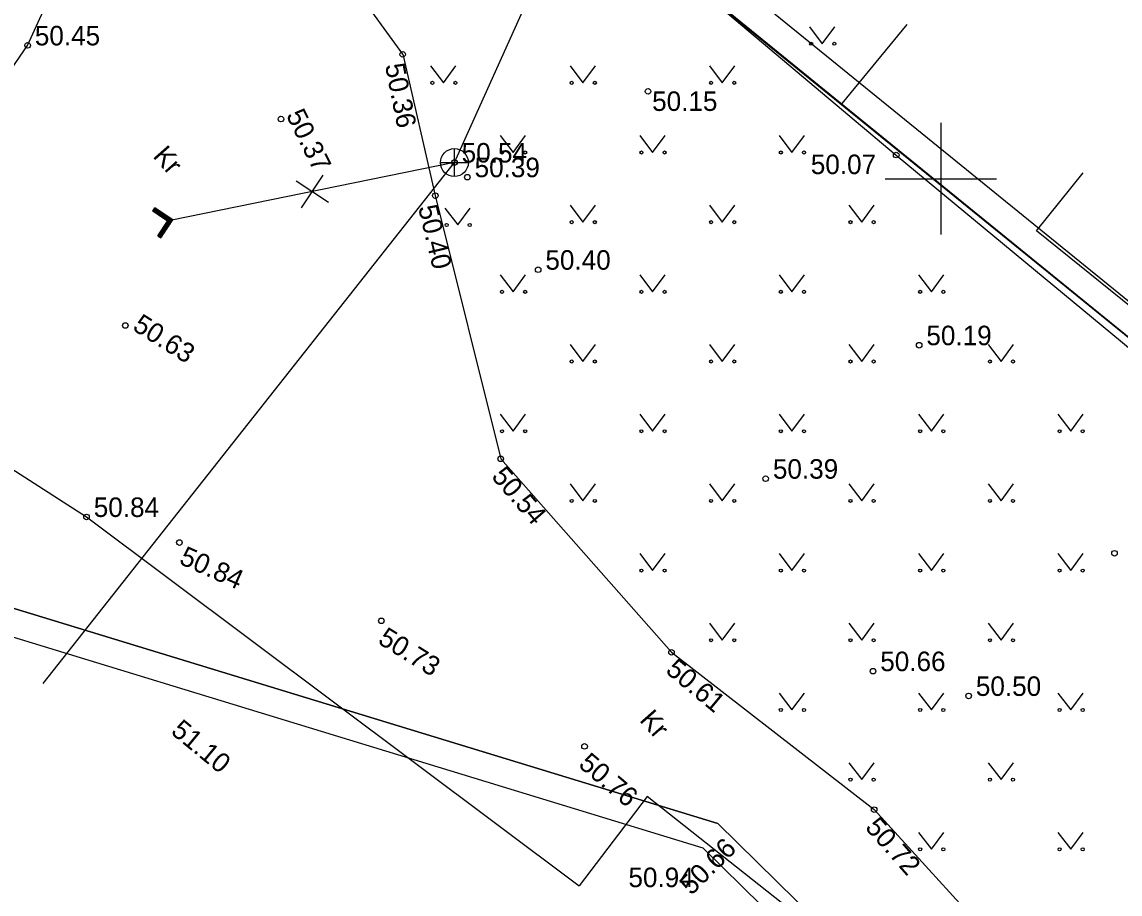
# Model space of a CAD drawing. Extents: x 640876 to 641418, y 6455595 to 6456085.
# Drawn here: x 641167.04 to 641206.43, y 6455774.33 to 6455805.62 of the extents above; entities that cross this region are included whole.
import ezdxf

# ---------------------------------------------------------------- set-up
doc = ezdxf.new("R2010")
doc.units = 0
for name, color, linetype in [('AED', 7, 'Continuous'), ('HALJASTUS', 7, 'Continuous'), ('HOONE', 7, 'Continuous'), ('KKAEV', 7, 'Continuous'), ('KORGUS', 7, 'Continuous'), ('KTRASS', 7, 'Continuous'), ('MOOTKORG', 7, 'Continuous'), ('MOOTMPUNKT', 7, 'Continuous'), ('MOOTPIIR', 7, 'Continuous'), ('PIIR', 7, 'Continuous'), ('SKTRASS', 7, 'Continuous'), ('TEE', 7, 'Continuous'), ('VORK', 7, 'Continuous')]:
    doc.layers.add(name, color=color, linetype=linetype)

msp = doc.modelspace()

# ---------------------------------------------------------------- linework, layer by layer
at = {"layer": 'AED'}
msp.add_lwpolyline([(641190.92, 6455807.146), (641198.401, 6455800.847), (641210.748, 6455790.622), (641234.804, 6455771.169), (641236.98, 6455773.379)], dxfattribs=at)
at = {"layer": 'HALJASTUS'}
for p, q in [((641195.287, 6455805.447), (641195.75, 6455804.84)), ((641195.75, 6455804.84), (641196.196, 6455805.447)), ((641181.699, 6455804.047), (641182.162, 6455803.44)), ((641182.162, 6455803.44), (641182.608, 6455804.047)), ((641186.699, 6455804.047), (641187.162, 6455803.44)), ((641187.162, 6455803.44), (641187.608, 6455804.047)), ((641191.699, 6455804.047), (641192.162, 6455803.44)), ((641192.162, 6455803.44), (641192.608, 6455804.047)), ((641184.199, 6455801.547), (641184.662, 6455800.94)), ((641184.662, 6455800.94), (641185.108, 6455801.547)), ((641189.199, 6455801.547), (641189.662, 6455800.94)), ((641189.662, 6455800.94), (641190.108, 6455801.547)), ((641194.199, 6455801.547), (641194.662, 6455800.94)), ((641194.662, 6455800.94), (641195.108, 6455801.547)), ((641182.21, 6455798.947), (641182.673, 6455798.34)), ((641182.673, 6455798.34), (641183.119, 6455798.947)), ((641186.699, 6455799.047), (641187.162, 6455798.44)), ((641187.162, 6455798.44), (641187.608, 6455799.047)), ((641191.699, 6455799.047), (641192.162, 6455798.44)), ((641192.162, 6455798.44), (641192.608, 6455799.047)), ((641196.699, 6455799.047), (641197.162, 6455798.44)), ((641197.162, 6455798.44), (641197.608, 6455799.047)), ((641184.199, 6455796.547), (641184.662, 6455795.94)), ((641184.662, 6455795.94), (641185.108, 6455796.547)), ((641189.199, 6455796.547), (641189.662, 6455795.94)), ((641189.662, 6455795.94), (641190.108, 6455796.547)), ((641194.199, 6455796.547), (641194.662, 6455795.94)), ((641194.662, 6455795.94), (641195.108, 6455796.547)), ((641199.199, 6455796.547), (641199.662, 6455795.94)), ((641199.662, 6455795.94), (641200.108, 6455796.547)), ((641186.699, 6455794.047), (641187.162, 6455793.44)), ((641187.162, 6455793.44), (641187.608, 6455794.047)), ((641191.699, 6455794.047), (641192.162, 6455793.44)), ((641192.162, 6455793.44), (641192.608, 6455794.047)), ((641196.699, 6455794.047), (641197.162, 6455793.44)), ((641197.162, 6455793.44), (641197.608, 6455794.047)), ((641201.699, 6455794.047), (641202.162, 6455793.44)), ((641202.162, 6455793.44), (641202.608, 6455794.047)), ((641184.199, 6455791.547), (641184.662, 6455790.94)), ((641184.662, 6455790.94), (641185.108, 6455791.547)), ((641189.199, 6455791.547), (641189.662, 6455790.94)), ((641189.662, 6455790.94), (641190.108, 6455791.547)), ((641194.199, 6455791.547), (641194.662, 6455790.94)), ((641194.662, 6455790.94), (641195.108, 6455791.547)), ((641199.199, 6455791.547), (641199.662, 6455790.94)), ((641199.662, 6455790.94), (641200.108, 6455791.547)), ((641204.199, 6455791.547), (641204.662, 6455790.94)), ((641204.662, 6455790.94), (641205.108, 6455791.547)), ((641186.699, 6455789.047), (641187.162, 6455788.44)), ((641187.162, 6455788.44), (641187.608, 6455789.047)), ((641191.699, 6455789.047), (641192.162, 6455788.44)), ((641192.162, 6455788.44), (641192.608, 6455789.047)), ((641196.699, 6455789.047), (641197.162, 6455788.44)), ((641197.162, 6455788.44), (641197.608, 6455789.047)), ((641201.699, 6455789.047), (641202.162, 6455788.44)), ((641202.162, 6455788.44), (641202.608, 6455789.047)), ((641189.199, 6455786.547), (641189.662, 6455785.94)), ((641189.662, 6455785.94), (641190.108, 6455786.547)), ((641194.199, 6455786.547), (641194.662, 6455785.94)), ((641194.662, 6455785.94), (641195.108, 6455786.547)), ((641199.199, 6455786.547), (641199.662, 6455785.94)), ((641199.662, 6455785.94), (641200.108, 6455786.547)), ((641204.199, 6455786.547), (641204.662, 6455785.94)), ((641204.662, 6455785.94), (641205.108, 6455786.547)), ((641191.699, 6455784.047), (641192.162, 6455783.44)), ((641192.162, 6455783.44), (641192.608, 6455784.047)), ((641196.699, 6455784.047), (641197.162, 6455783.44)), ((641197.162, 6455783.44), (641197.608, 6455784.047)), ((641201.699, 6455784.047), (641202.162, 6455783.44)), ((641202.162, 6455783.44), (641202.608, 6455784.047)), ((641194.199, 6455781.547), (641194.662, 6455780.94)), ((641194.662, 6455780.94), (641195.108, 6455781.547)), ((641199.199, 6455781.547), (641199.662, 6455780.94)), ((641199.662, 6455780.94), (641200.108, 6455781.547)), ((641204.199, 6455781.547), (641204.662, 6455780.94)), ((641204.662, 6455780.94), (641205.108, 6455781.547)), ((641196.699, 6455779.047), (641197.162, 6455778.44)), ((641197.162, 6455778.44), (641197.608, 6455779.047)), ((641201.699, 6455779.047), (641202.162, 6455778.44)), ((641202.162, 6455778.44), (641202.608, 6455779.047)), ((641199.199, 6455776.547), (641199.662, 6455775.94)), ((641199.662, 6455775.94), (641200.108, 6455776.547)), ((641204.199, 6455776.547), (641204.662, 6455775.94)), ((641204.662, 6455775.94), (641205.108, 6455776.547))]:
    msp.add_line(p, q, dxfattribs=at)
msp.add_lwpolyline([(641196.46, 6455802.7), (641198.791, 6455805.527)], dxfattribs=at)
for centre in [(641195.349, 6455804.84), (641196.178, 6455804.84), (641181.761, 6455803.44), (641182.59, 6455803.44), (641186.761, 6455803.44), (641187.59, 6455803.44), (641191.761, 6455803.44), (641192.59, 6455803.44), (641184.261, 6455800.94), (641185.09, 6455800.94), (641189.261, 6455800.94), (641190.09, 6455800.94), (641194.261, 6455800.94), (641195.09, 6455800.94), (641182.272, 6455798.34), (641183.101, 6455798.34), (641186.761, 6455798.44), (641187.59, 6455798.44), (641191.761, 6455798.44), (641192.59, 6455798.44), (641196.761, 6455798.44), (641197.59, 6455798.44), (641184.261, 6455795.94), (641185.09, 6455795.94), (641189.261, 6455795.94), (641190.09, 6455795.94), (641194.261, 6455795.94), (641195.09, 6455795.94), (641199.261, 6455795.94), (641200.09, 6455795.94), (641186.761, 6455793.44), (641187.59, 6455793.44), (641191.761, 6455793.44), (641192.59, 6455793.44), (641196.761, 6455793.44), (641197.59, 6455793.44), (641201.761, 6455793.44), (641202.59, 6455793.44), (641184.261, 6455790.94), (641185.09, 6455790.94), (641189.261, 6455790.94), (641190.09, 6455790.94), (641194.261, 6455790.94), (641195.09, 6455790.94), (641199.261, 6455790.94), (641200.09, 6455790.94), (641204.261, 6455790.94), (641205.09, 6455790.94), (641186.761, 6455788.44), (641187.59, 6455788.44), (641191.761, 6455788.44), (641192.59, 6455788.44), (641196.761, 6455788.44), (641197.59, 6455788.44), (641201.761, 6455788.44), (641202.59, 6455788.44), (641189.261, 6455785.94), (641190.09, 6455785.94), (641194.261, 6455785.94), (641195.09, 6455785.94), (641199.261, 6455785.94), (641200.09, 6455785.94), (641204.261, 6455785.94), (641205.09, 6455785.94), (641191.761, 6455783.44), (641192.59, 6455783.44), (641196.761, 6455783.44), (641197.59, 6455783.44), (641201.761, 6455783.44), (641202.59, 6455783.44), (641194.261, 6455780.94), (641195.09, 6455780.94), (641199.261, 6455780.94), (641200.09, 6455780.94), (641204.261, 6455780.94), (641205.09, 6455780.94), (641196.761, 6455778.44), (641197.59, 6455778.44), (641201.761, 6455778.44), (641202.59, 6455778.44), (641199.261, 6455775.94), (641200.09, 6455775.94), (641204.261, 6455775.94), (641205.09, 6455775.94)]:
    msp.add_circle(centre, 0.055, dxfattribs=at)
at = {"layer": 'HOONE'}
msp.add_lwpolyline([(641211.46, 6455791.66), (641203.43, 6455798.13), (641205.106, 6455800.211)], dxfattribs=at)
at = {"layer": 'KKAEV'}
for p, q in [((641182.553, 6455800.079), (641182.553, 6455801.079)), ((641182.053, 6455800.579), (641183.053, 6455800.579))]:
    msp.add_line(p, q, dxfattribs=at)
msp.add_circle((641182.553, 6455800.579), 0.5, dxfattribs=at)
at = {"layer": 'KORGUS'}
for centre in [(641180.696, 6455804.462), (641189.499, 6455803.133), (641176.329, 6455802.139), (641198.401, 6455800.847), (641183.016, 6455800.053), (641181.867, 6455799.392), (641185.556, 6455796.734), (641170.748, 6455794.733), (641199.223, 6455794.025), (641184.213, 6455789.95), (641193.717, 6455789.236), (641172.688, 6455786.945), (641206.231, 6455786.56), (641179.931, 6455784.135), (641190.34, 6455783.007), (641197.568, 6455782.332), (641200.998, 6455781.443), (641187.221, 6455779.631), (641197.609, 6455777.363)]:
    msp.add_circle(centre, 0.1, dxfattribs=at)
at = {"layer": 'KTRASS'}
for p, q in [((641182.553, 6455800.579), (641188.359, 6455813.48)), ((641167.805, 6455781.893), (641182.553, 6455800.579))]:
    msp.add_line(p, q, dxfattribs=at)
at = {"layer": 'MOOTMPUNKT'}
for centre in [(641167.241, 6455804.782), (641182.553, 6455800.579), (641169.355, 6455787.863)]:
    msp.add_circle(centre, 0.1, dxfattribs=at)
at = {"layer": 'MOOTPIIR'}
msp.add_lwpolyline([(641060.916, 6455895.936), (641100.061, 6455950.482), (641099.586, 6455952.159), (641069.132, 6455984.035), (641066.132, 6455988.623), (641076.463, 6456005.049), (641230.642, 6456010.048), (641237.36, 6455995.24), (641237.24, 6455992.81), (641236.258, 6455990.888), (641229.041, 6455971.315), (641203.026, 6455909.57), (641225.257, 6455906.847), (641239.512, 6455898.491), (641200.195, 6455851.697), (641192.016, 6455859.099), (641169.785, 6455829.138), (641192.025, 6455807.568), (641252.96, 6455758.075), (641231.388, 6455736.74), (641191.474, 6455775.975), (641152.419, 6455787.914), (641136.351, 6455788.307), (641049.066, 6455856.043)], dxfattribs=at)
at = {"layer": 'PIIR'}
for points in [[(641216.67, 6455752.61), (641192, 6455776.86), (641152.58, 6455788.91), (641136.9, 6455789.33), (641119.28, 6455802.72), (641101.72, 6455816.27), (641098.61, 6455818.83), (641124.03, 6455849.78), (641139.51, 6455868.99), (641157, 6455885.69), (641191.84, 6455860.59), (641168.46, 6455829.03), (641191.37, 6455806.79), (641234.69, 6455771.62)], [(641234.68, 6455771.59), (641191.36, 6455806.82), (641199.12, 6455815.36), (641207.91, 6455825.07), (641250.06, 6455787.79)], [(641216.67, 6455752.61), (641182.28, 6455716.38), (641177.47, 6455716.39), (641127.83, 6455755.09), (641138.89, 6455768.28), (641129.48, 6455779.82), (641136.9, 6455789.33), (641152.58, 6455788.91), (641192, 6455776.86)]]:
    msp.add_lwpolyline(points, close=True, dxfattribs=at)
at = {"layer": 'SKTRASS'}
for p, q in [((641182.553, 6455800.579), (641172.357, 6455798.501)), ((641176.871, 6455799.926), (641178.039, 6455799.154)), ((641177.069, 6455798.956), (641177.841, 6455800.124)), ((641171.728, 6455798.832), (641171.807, 6455798.951)), ((641172.258, 6455798.481), (641171.728, 6455798.832)), ((641171.733, 6455798.829), (641171.871, 6455798.908)), ((641171.753, 6455798.869), (641171.848, 6455798.923)), ((641171.756, 6455798.813), (641171.894, 6455798.893)), ((641172.357, 6455798.501), (641171.767, 6455798.891)), ((641171.779, 6455798.798), (641171.918, 6455798.877)), ((641171.783, 6455798.915), (641171.824, 6455798.939)), ((641171.803, 6455798.783), (641171.941, 6455798.862)), ((641172.456, 6455798.521), (641171.807, 6455798.951)), ((641171.826, 6455798.767), (641171.964, 6455798.846)), ((641171.849, 6455798.752), (641171.988, 6455798.831)), ((641171.873, 6455798.736), (641172.011, 6455798.815)), ((641171.896, 6455798.721), (641172.034, 6455798.8)), ((641171.919, 6455798.705), (641172.058, 6455798.784)), ((641171.943, 6455798.69), (641172.081, 6455798.769)), ((641171.966, 6455798.674), (641172.105, 6455798.754)), ((641171.99, 6455798.659), (641172.128, 6455798.738)), ((641172.013, 6455798.644), (641172.151, 6455798.723)), ((641172.036, 6455798.628), (641172.175, 6455798.707)), ((641171.908, 6455797.951), (641172.258, 6455798.481)), ((641171.967, 6455797.911), (641172.357, 6455798.501)), ((641172.026, 6455797.872), (641172.456, 6455798.521)), ((641172.06, 6455798.613), (641172.198, 6455798.692)), ((641172.06, 6455798.181), (641172.334, 6455798.338)), ((641172.083, 6455798.597), (641172.221, 6455798.676)), ((641172.09, 6455798.227), (641172.365, 6455798.384)), ((641172.106, 6455798.582), (641172.245, 6455798.661)), ((641172.121, 6455798.273), (641172.396, 6455798.43)), ((641172.13, 6455798.566), (641172.268, 6455798.645)), ((641172.152, 6455798.32), (641172.426, 6455798.477)), ((641172.153, 6455798.551), (641172.291, 6455798.63)), ((641172.176, 6455798.535), (641172.315, 6455798.615)), ((641172.182, 6455798.366), (641172.455, 6455798.522)), ((641172.2, 6455798.52), (641172.338, 6455798.599)), ((641172.213, 6455798.412), (641172.431, 6455798.537)), ((641172.223, 6455798.505), (641172.361, 6455798.584)), ((641172.244, 6455798.459), (641172.408, 6455798.553)), ((641172.246, 6455798.489), (641172.385, 6455798.568)), ((641171.908, 6455797.95), (641172.181, 6455798.106)), ((641171.908, 6455797.951), (641172.026, 6455797.872)), ((641171.932, 6455797.935), (641172.15, 6455798.06)), ((641171.937, 6455797.995), (641172.212, 6455798.152)), ((641171.955, 6455797.919), (641172.12, 6455798.013)), ((641171.968, 6455798.042), (641172.242, 6455798.199)), ((641171.979, 6455797.904), (641172.089, 6455797.967)), ((641171.998, 6455798.088), (641172.273, 6455798.245)), ((641172.002, 6455797.888), (641172.059, 6455797.921)), ((641172.029, 6455798.134), (641172.304, 6455798.291))]:
    msp.add_line(p, q, dxfattribs=at)
at = {"layer": 'TEE'}
for points in [[(641180.696, 6455804.462), (641172.269, 6455816.081), (641168.21, 6455822.681), (641167.472, 6455824.588), (641166.769, 6455828.637), (641167.7, 6455831.443), (641172.464, 6455837.156), (641175.489, 6455842.795)], [(641160.373, 6455794.57), (641161.446, 6455796), (641164.176, 6455800.333), (641167.241, 6455804.782), (641168.195, 6455806.885), (641168.038, 6455808.236), (641167.235, 6455809.577)], [(641180.696, 6455804.462), (641181.867, 6455799.392), (641184.213, 6455789.95), (641190.34, 6455783.007), (641197.609, 6455777.363), (641202.64, 6455771.843), (641204.424, 6455768.853), (641206.274, 6455763.164)], [(641160.099, 6455794.273), (641164.082, 6455791.256), (641169.355, 6455787.863), (641187.027, 6455774.627)], [(641210.623, 6455756.753), (641209.995, 6455759.033), (641206.274, 6455763.164), (641201.573, 6455767.409), (641194.555, 6455773.807), (641189.469, 6455777.839), (641187.027, 6455774.627)]]:
    msp.add_lwpolyline(points, dxfattribs=at)
at = {"layer": 'VORK'}
for p, q in [((641200, 6455802), (641200, 6455798)), ((641198, 6455800), (641202, 6455800))]:
    msp.add_line(p, q, dxfattribs=at)

# ---------------------------------------------------------------- texts
at = {"layer": 'KORGUS'}
for s, rotation, p in [(' 50.36', 281.1442, (641180.009, 6455804.327)), (' 50.37', 296.2367, (641176.386, 6455802.518)), (' 50.40', 283.4362, (641181.186, 6455799.229)), (' 50.63', 327.8028, (641170.748, 6455794.733)), (' 50.54', 310.7051, (641183.682, 6455789.493)), (' 50.84', 335.9575, (641172.403, 6455786.306)), (' 50.73', 328.142, (641179.546, 6455783.488)), (' 50.61', 320.1663, (641189.892, 6455782.469)), (' 51.10', 320.5148, (641172.145, 6455780.278)), (' 50.76', 319.702, (641186.768, 6455779.097)), (' 50.72', 311.4716, (641197.085, 6455776.899)), (' 50.66', 44.8361, (641190.866, 6455774.079))]:
    msp.add_text(s, height=0.7, rotation=rotation, dxfattribs=at).set_placement(p)
for s, p in [(' 50.15', (641189.385, 6455802.431)), (' 50.39', (641183.016, 6455800.053)), (' 50.07', (641195.077, 6455800.164)), (' 50.40', (641185.556, 6455796.734)), (' 50.19', (641199.223, 6455794.025)), (' 50.39', (641193.717, 6455789.236)), (' 50.66', (641197.568, 6455782.332)), (' 50.50', (641200.998, 6455781.443))]:
    msp.add_text(s, height=0.7, dxfattribs=at).set_placement(p)
at = {"layer": 'MOOTKORG'}
for s, p in [(' 50.45', (641167.241, 6455804.782)), (' 50.54', (641182.553, 6455800.579)), (' 50.84', (641169.355, 6455787.863)), (' 50.94', (641188.535, 6455774.582))]:
    msp.add_text(s, height=0.7, dxfattribs=at).set_placement(p)
at = {"layer": 'TEE'}
for p in [(641171.708, 6455800.794), (641189.164, 6455780.56)]:
    msp.add_text('Kr', height=0.7, rotation=311.4262, dxfattribs=at).set_placement(p)

doc.saveas('drawing.dxf')
